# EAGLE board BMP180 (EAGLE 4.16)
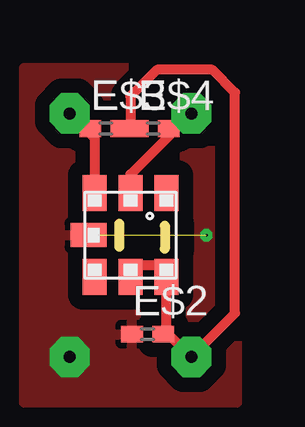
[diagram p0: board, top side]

Size 1.91 x 1.03 mm. Coordinates in mm from the lower left corner, seen from the top.
Outline: 1.91,0.95 1.91,0
Outline: 0,1.03 0,0.08
Copper layers (1*16): Top 0.035mm / dielectric 1.5mm / Bottom 0.035mm
Design rules "default": minimum track width 10mil, minimum drill 24mil, track to track 8mil, track to pad 8mil, pad to pad 8mil, via to via 8mil, smd to smd 8mil, copper to edge 40mil, drill to drill 8mil, minimum pad ring 10mil, minimum via ring 8mil, stop-mask expansion 4mil, vias tented up to drill 0mil, thermal gap 10mil

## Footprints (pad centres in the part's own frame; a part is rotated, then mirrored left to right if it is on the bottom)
BMP180 = smd 1 x 1.5: 1 -1.5,-1.75; 2 0,-1.75; 3 1.5,-1.75; 4 1.5,1.75; 5 0,1.75; 6 -1.5,1.75 | smd 1.5 x 1: 7 -1.75,0
C0402 = smd 0.9 x 0.7: 1 -0.65,0; 2 0.65,0

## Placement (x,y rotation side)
E$1  [BMP180]  0.48,0.56 0 top
E$2  [C0402]  not placed on the board
E$3  [C0402]  not placed on the board
E$4  [C0402]  not placed on the board

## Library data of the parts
E$1 = bosch
E$2-E$4 = ref-packages

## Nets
GND: E$1.7 E$2.1

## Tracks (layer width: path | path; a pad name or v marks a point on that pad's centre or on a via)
GND  (via drill 0.1, 0.5 pad 1.68)  (1 unrouted)
  other vias: -2.06,-4.52 3.65,0.56
  pour Top (isolate 0.61): -3.97,-6.43 -3.97,7.54 4.92,7.54 4.92,-6.43
S$2  (via drill 0.5 pad 1.68)
  Top 0.406: 0.48,-0.71 1.98,-0.71 1.98,-3.49 v3.02,-4.52
S$3  (via drill 0.5 pad 1.68)
  Top 0.406: v3.02,5.64 0.48,3.1 0.48,2.46
S$4  (via drill 0.5 pad 1.68)
  Top 0.406: v-2.06,5.64 -1.03,4.6 -1.03,2.7
S$5
  Top 0.406: 0.48,4.92 0.48,6.35 1.59,7.46 3.89,7.46 4.84,6.51 4.84,-2.7 3.02,-4.52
